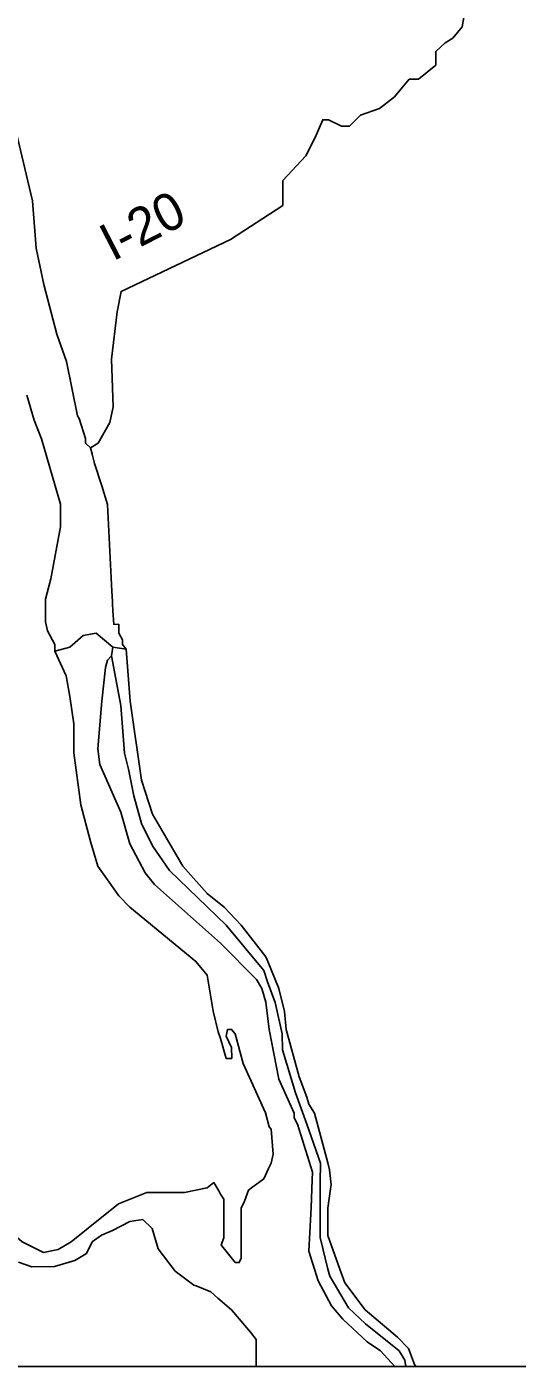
# Model space of a CAD drawing. Extents: x 1936118 to 1997618, y 780614 to 828614.
# Drawn here: x 1977726 to 1985605, y 788861 to 810402 of the extents above; entities that cross this region are included whole.
import ezdxf

# ---------------------------------------------------------------- set-up
doc = ezdxf.new("R2010")
doc.units = 0
for name, color, linetype in [('RD_EX_H2O_BlueLn', 7, 'Continuous'), ('RD_SHT_Misc3', 7, 'Continuous'), ('RD_SHT_ShtClip', 7, 'Continuous')]:
    doc.layers.add(name, color=color, linetype=linetype)

msp = doc.modelspace()

# ---------------------------------------------------------------- linework, layer by layer
at = {"layer": 'RD_EX_H2O_BlueLn'}
for points in [[(1973253, 817137), (1973407, 816991), (1973584, 816594), (1973887, 815756), (1974339, 815098), (1974706, 814408), (1974918, 814125), (1975309, 813500), (1975457, 813315), (1975643, 812956), (1976517, 811570), (1976734, 811173), (1977001, 810446), (1977217, 809753), (1977458, 809171), (1977548, 808736), (1977820, 807606), (1977875, 806845), (1977998, 806260), (1978211, 805465), (1978363, 805022), (1978540, 804151), (1978567, 804110), (1978671, 803787)], [(1985270, 811384), (1985270, 811381), (1984750, 810550), (1984723, 810402), (1984570, 810222), (1984448, 810146), (1984298, 810008), (1984296, 809787), (1984022, 809563), (1983872, 809563), (1983634, 809275), (1983391, 809092), (1983086, 808985), (1982910, 808808), (1982783, 808808), (1982571, 808907), (1982481, 808908), (1982361, 808623), (1982210, 808328), (1981841, 807931), (1981841, 807833)], [(1981841, 807833), (1981840, 807533), (1980999, 806982), (1979242, 806150), (1979179, 805823), (1979089, 805060), (1979116, 804294), (1979058, 804043), (1978871, 803713), (1978752, 803637)], [(1977724, 804480), (1977843, 804082), (1977962, 803783), (1978267, 802730), (1978266, 802368), (1978113, 801528), (1978025, 801205), (1978026, 800840), (1978056, 800697), (1978177, 800473), (1978177, 800368), (1978360, 799970), (1978418, 799641), (1978481, 799203), (1978482, 798732), (1978594, 797897), (1978747, 797309), (1978867, 796911), (1979205, 796436), (1979383, 796254), (1980443, 795382), (1980622, 795163), (1980719, 794581), (1980802, 794251), (1980839, 794143), (1980927, 793823), (1981018, 793822), (1981016, 794000), (1980928, 794182), (1980953, 794290), (1981016, 794290), (1981075, 794218), (1981202, 793741), (1981562, 792946), (1981620, 792722), (1981653, 792684), (1981683, 792287), (1981653, 792140), (1981611, 792054)], [(1978671, 803787), (1978667, 803716)], [(1978667, 803716), (1978676, 803708)], [(1978676, 803708), (1978752, 803637)], [(1978752, 803637), (1978775, 803542)], [(1978775, 803542), (1978777, 803536)], [(1978777, 803536), (1978815, 803386), (1978934, 803025), (1979023, 802727), (1979094, 801333)], [(1979094, 801333), (1979102, 801169), (1979104, 801132)], [(1979104, 801132), (1979110, 801014), (1979114, 800946), (1979123, 800799), (1979207, 800803)], [(1979207, 800803), (1979207, 800754)], [(1979207, 800754), (1979207, 800658), (1979264, 800550), (1979265, 800474), (1979324, 800402), (1979385, 799563), (1979568, 798295), (1979748, 797746), (1980235, 796911), (1980623, 796474), (1980898, 796253), (1981170, 795963), (1981566, 795457), (1981598, 795382), (1981775, 794946), (1981869, 794578), (1981896, 794288), (1982104, 793527), (1982225, 793198), (1982258, 793090), (1982351, 792943), (1982563, 792143), (1982592, 792033), (1982617, 791790)], [(1979111, 800435), (1978839, 800656), (1978633, 800620), (1978419, 800435), (1978177, 800368)], [(1979085, 800292), (1979023, 800222), (1978992, 800108), (1978934, 799563), (1978870, 798799), (1978900, 798547), (1979238, 797783), (1979383, 797272), (1979626, 796805), (1979777, 796620), (1980838, 795673), (1981417, 795091), (1981500, 794946), (1981565, 794725), (1981621, 794288), (1981774, 793492), (1982020, 792943), (1982021, 792867), (1982078, 792765), (1982319, 791996), (1982313, 791870)], [(1979085, 800292), (1979111, 800435)], [(1982442, 791836), (1982443, 792142), (1982225, 792765), (1982046, 793272), (1981833, 793961), (1981831, 794219), (1981715, 794724), (1981595, 795053), (1981534, 795238), (1980928, 795962), (1980020, 796843), (1979746, 797238), (1979567, 797599), (1979448, 798043), (1979360, 798472), (1979294, 798729), (1979237, 799493), (1979085, 800292)], [(1979111, 800435), (1979324, 800402)], [(1972887, 793307), (1973137, 793277), (1973565, 793461), (1973839, 793461), (1974231, 793317), (1974747, 792949), (1975021, 792840), (1975294, 792771), (1975688, 792726), (1976079, 792473), (1976383, 792182), (1976624, 791854), (1977019, 791420), (1977654, 790875), (1977996, 790703)], [(1981611, 792054), (1981532, 791889), (1981335, 791742)], [(1978231, 790750), (1978437, 790875), (1978713, 791096), (1979202, 791487), (1979653, 791670), (1980258, 791670), (1980622, 791745), (1980732, 791828)], [(1980732, 791828), (1980811, 791693)], [(1980811, 791693), (1980839, 791644)], [(1981335, 791742), (1981288, 791707), (1981226, 791529), (1981168, 791415), (1981168, 791344)], [(1982313, 791870), (1982294, 791425)], [(1982441, 791566), (1982442, 791836)], [(1982605, 791725), (1982563, 791415)], [(1982617, 791790), (1982605, 791725)], [(1980839, 791644), (1980893, 791561)], [(1980893, 791561), (1980893, 791095)], [(1982441, 791394), (1982441, 791566)], [(1977595, 790548), (1977807, 790475), (1978169, 790478), (1978499, 790578), (1978685, 790690), (1978775, 790874), (1978926, 790982), (1979105, 791056), (1979380, 791201), (1979589, 791234), (1979743, 791088), (1979837, 790761), (1980110, 790402), (1980409, 790180)], [(1981168, 791335), (1981169, 790614), (1981140, 790543), (1981074, 790544)], [(1981168, 791344), (1981168, 791335)], [(1982288, 791324), (1982258, 790727), (1982348, 790437)], [(1982294, 791425), (1982288, 791324)], [(1982288, 791324), (1982288, 791324)], [(1982440, 791331), (1982441, 791394)], [(1982440, 791330), (1982440, 791331)], [(1982565, 790437), (1982440, 790943), (1982440, 791330)], [(1982563, 791415), (1982563, 791343)], [(1982563, 791343), (1982563, 791342)], [(1982563, 791342), (1982563, 790979), (1982755, 790437)], [(1980893, 791095), (1980894, 790941), (1980851, 790825)], [(1980851, 790825), (1980860, 790813)], [(1980860, 790813), (1981074, 790544)], [(1977996, 790703), (1978231, 790750)], [(1982348, 790437), (1982407, 790246), (1982624, 789849), (1982803, 789633), (1983196, 789268), (1983407, 789123), (1983642, 788874)], [(1983817, 788874), (1983801, 788975), (1983711, 789121), (1983166, 789557), (1982897, 789816), (1982594, 790322), (1982565, 790437)], [(1982755, 790437), (1982834, 790215), (1983165, 789781), (1983680, 789344), (1983858, 789161), (1983954, 788906), (1983977, 788874)], [(1980409, 790180), (1980446, 790166)], [(1980446, 790166), (1980683, 790071), (1980798, 789970)], [(1980798, 789970), (1981014, 789782)], [(1981014, 789782), (1981320, 789421), (1981413, 789307), (1981413, 788874)]]:
    msp.add_lwpolyline(points, dxfattribs=at)
at = {"layer": 'RD_SHT_ShtClip'}
msp.add_lwpolyline([(1936683, 827674), (1979343, 827674), (1979343, 811384), (1997169, 811384), (1997169, 788874), (1947786, 788874), (1945387, 788861), (1936683, 788861)], close=True, dxfattribs=at)

# ---------------------------------------------------------------- texts
at = {"layer": 'RD_SHT_Misc3'}
msp.add_text('I-20', height=600, rotation=27.2878, dxfattribs=at).set_placement((1979105, 806627))

doc.saveas('drawing.dxf')
